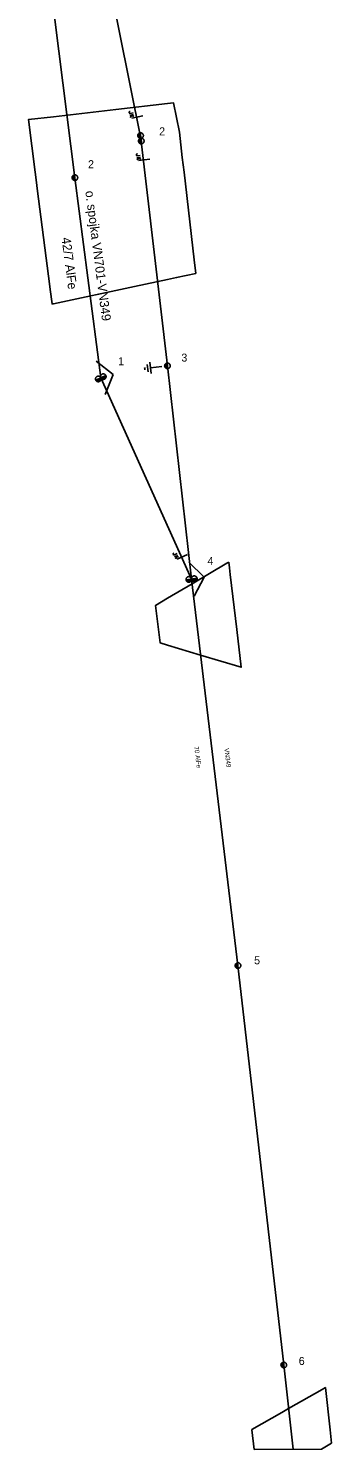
# Model space of a CAD drawing. Extents: x -536397 to -535454, y -1201642 to -1200953.
# Drawn here: x -536243 to -536176.6, y -1201641.8 to -1201331.1 of the extents above; entities that cross this region are included whole.
import ezdxf

# ---------------------------------------------------------------- set-up
doc = ezdxf.new("R2010")
doc.units = 0
for name, color, linetype in [('Vrstva 1', 7, 'Continuous'), ('Vrstva 13', 7, 'Continuous'), ('Vrstva 14', 7, 'Continuous'), ('Vrstva 15', 7, 'Continuous'), ('Vrstva 18', 7, 'Continuous'), ('Vrstva 2', 7, 'Continuous'), ('Vrstva 3', 7, 'Continuous'), ('Vrstva 35', 7, 'Continuous'), ('Vrstva 52', 7, 'Continuous'), ('Vrstva 53', 7, 'Continuous'), ('Vrstva 54', 7, 'Continuous')]:
    doc.layers.add(name, color=color, linetype=linetype)

# ---------------------------------------------------------------- blocks, each defined once
blk = doc.blocks.new('VN840')
at = {"layer": 'Vrstva 15'}
for points in [[(-0.01, 1.41), (-0.01, -1.09)], [(-1.51, -1.24), (-1.51, -1.15)], [(-1.48, -1.35), (-1.51, -1.24)], [(-1.33, -1.42), (-1.48, -1.35)], [(-1.27, -1.42), (-1.33, -1.42)], [(-1.13, -1.35), (-1.27, -1.42)], [(-1.09, -1.24), (-1.13, -1.35)], [(-1.09, -0.59), (-1.09, -1.24)], [(-0.68, -0.59), (-0.68, -1.42)], [(-0.68, -1.11), (-0.27, -0.59)], [(-0.54, -0.94), (-0.2, -1.42)]]:
    blk.add_lwpolyline(points, dxfattribs=at)
blk = doc.blocks.new('VN860')
at = {"layer": 'Vrstva 15'}
for points in [[(-3.74, 0), (0.01, 2.82)], [(0.01, 2.82), (3.76, 0)]]:
    blk.add_lwpolyline(points, dxfattribs=at)
blk = doc.blocks.new('VN440')
at = {"layer": 'Vrstva 2'}
for points in [[(1.22, 0), (1.21, 0.13), (1.19, 0.25), (1.16, 0.38), (1.11, 0.5), (1.05, 0.61), (0.98, 0.72), (0.9, 0.82), (0.81, 0.91), (0.71, 0.99), (0.6, 1.06), (0.49, 1.12), (0.37, 1.16), (0.25, 1.2), (0.12, 1.22), (-0.01, 1.22), (-0.14, 1.22), (-0.26, 1.2), (-0.39, 1.16), (-0.51, 1.12), (-0.62, 1.06), (-0.73, 0.99), (-0.83, 0.91), (-0.92, 0.82), (-1, 0.72), (-1.07, 0.61), (-1.13, 0.5), (-1.18, 0.38), (-1.21, 0.25), (-1.23, 0.13), (-1.24, 0), (-1.23, -0.13), (-1.21, -0.26), (-1.18, -0.38), (-1.13, -0.5), (-1.07, -0.62), (-1, -0.73), (-0.92, -0.83), (-0.83, -0.92), (-0.73, -1), (-0.62, -1.07), (-0.51, -1.13), (-0.39, -1.17), (-0.26, -1.2), (-0.14, -1.23), (-0.01, -1.23), (0.12, -1.23), (0.25, -1.2), (0.37, -1.17), (0.49, -1.13), (0.6, -1.07), (0.71, -1), (0.81, -0.92), (0.9, -0.83), (0.98, -0.73), (1.05, -0.62), (1.11, -0.5), (1.16, -0.38), (1.19, -0.26), (1.21, -0.13), (1.22, 0)], [(-1.24, 0), (1.22, 0)], [(-1.18, -0.34), (1.1, -0.34)], [(-1.01, -0.63), (0.97, -0.63)], [(-0.74, -0.92), (0.68, -0.92)]]:
    blk.add_lwpolyline(points, dxfattribs=at)
blk = doc.blocks.new('VN810')
at = {"layer": 'Vrstva 14'}
for points in [[(0, -1.25), (0, -3.75)], [(1.25, -3.75), (-1.25, -3.75)], [(0.77, -4.37), (-0.8, -4.37)], [(0, -5), (-0.25, -5)], [(0.27, -5), (0, -5)]]:
    blk.add_lwpolyline(points, dxfattribs=at)
blk = doc.blocks.new('VN450')
at = {"layer": 'Vrstva 2'}
for points in [[(0, 0), (-0.01, 0.13), (-0.03, 0.25), (-0.06, 0.38), (-0.11, 0.5), (-0.16, 0.61), (-0.23, 0.72), (-0.31, 0.82), (-0.4, 0.91), (-0.5, 0.99), (-0.61, 1.06), (-0.72, 1.11), (-0.84, 1.16), (-0.97, 1.19), (-1.09, 1.21), (-1.22, 1.22), (-1.35, 1.21), (-1.47, 1.19), (-1.59, 1.16), (-1.71, 1.11), (-1.83, 1.06), (-1.93, 0.99), (-2.03, 0.91), (-2.12, 0.82), (-2.2, 0.72), (-2.27, 0.61), (-2.33, 0.5), (-2.38, 0.38), (-2.41, 0.25), (-2.43, 0.13), (-2.44, 0), (-2.43, -0.13), (-2.41, -0.25), (-2.38, -0.38), (-2.33, -0.5), (-2.27, -0.61), (-2.2, -0.72), (-2.12, -0.82), (-2.03, -0.91), (-1.93, -0.99), (-1.83, -1.06), (-1.71, -1.11), (-1.59, -1.16), (-1.47, -1.19), (-1.35, -1.21), (-1.22, -1.22), (-1.09, -1.21), (-0.97, -1.19), (-0.84, -1.16), (-0.72, -1.11), (-0.61, -1.06), (-0.5, -0.99), (-0.4, -0.91), (-0.31, -0.82), (-0.23, -0.72), (-0.16, -0.61), (-0.11, -0.5), (-0.06, -0.38), (-0.03, -0.25), (-0.01, -0.13), (0, 0)], [(-2.44, 0), (2.44, 0)], [(2.44, 0), (2.43, 0.13), (2.41, 0.25), (2.38, 0.38), (2.33, 0.5), (2.27, 0.61), (2.2, 0.72), (2.12, 0.82), (2.03, 0.91), (1.94, 0.99), (1.83, 1.06), (1.71, 1.11), (1.6, 1.16), (1.47, 1.19), (1.35, 1.21), (1.22, 1.22), (1.09, 1.21), (0.97, 1.19), (0.84, 1.16), (0.72, 1.11), (0.61, 1.06), (0.5, 0.99), (0.4, 0.91), (0.31, 0.82), (0.23, 0.72), (0.16, 0.61), (0.11, 0.5), (0.06, 0.38), (0.03, 0.25), (0.01, 0.13), (0, 0), (0.01, -0.13), (0.03, -0.25), (0.06, -0.38), (0.11, -0.5), (0.16, -0.61), (0.23, -0.72), (0.31, -0.82), (0.4, -0.91), (0.5, -0.99), (0.61, -1.06), (0.72, -1.11), (0.84, -1.16), (0.97, -1.19), (1.09, -1.21), (1.22, -1.22), (1.35, -1.21), (1.47, -1.19), (1.6, -1.16), (1.71, -1.11), (1.83, -1.06), (1.94, -0.99), (2.03, -0.91), (2.12, -0.82), (2.2, -0.72), (2.27, -0.61), (2.33, -0.5), (2.38, -0.38), (2.41, -0.25), (2.43, -0.13), (2.44, 0)], [(-2.4, -0.31), (-0.04, -0.31)], [(-2.26, -0.61), (-0.17, -0.61)], [(-2.01, -0.92), (-0.42, -0.92)], [(0.04, -0.31), (2.4, -0.31)], [(0.17, -0.61), (2.27, -0.61)], [(0.42, -0.92), (2.02, -0.92)]]:
    blk.add_lwpolyline(points, dxfattribs=at)

msp = doc.modelspace()

# ---------------------------------------------------------------- linework, layer by layer
at = {"layer": 'Vrstva 1'}
for points in [[(-536230.2, -1201296.37), (-536218.34, -1201355.12), (-536212.54, -1201404.88), (-536207.27, -1201451.49)], [(-536207.27, -1201451.49), (-536197.12, -1201536.02), (-536187.09, -1201623.35), (-536185.03, -1201641.79)]]:
    msp.add_lwpolyline(points, dxfattribs=at)
at = {"layer": 'Vrstva 35'}
for points in [[(-536223.8, -1201348.8), (-536212.5, -1201347.49), (-536211.24, -1201347.33), (-536209.94, -1201353.78), (-536209.3, -1201359.3), (-536208.92, -1201362.5), (-536206.69, -1201381.69), (-536206.34, -1201384.65), (-536210.55, -1201385.55), (-536212.5, -1201385.96), (-536219.72, -1201387.5), (-536237.5, -1201391.29), (-536237.79, -1201391.34), (-536238.2, -1201388.2), (-536238.29, -1201387.5), (-536241.06, -1201366.06), (-536241.22, -1201364.8), (-536241.51, -1201362.5), (-536242.96, -1201351.03), (-536237.5, -1201350.39)], [(-536199.14, -1201447.78), (-536199, -1201449), (-536198.83, -1201450.48), (-536198.83, -1201450.51), (-536198.82, -1201450.53), (-536197.38, -1201462.5), (-536196.39, -1201470.78), (-536205.28, -1201468.1), (-536212.5, -1201465.93), (-536214.16, -1201465.43), (-536214.3, -1201464.3), (-536214.51, -1201462.5), (-536215.14, -1201457.24), (-536212.5, -1201455.68), (-536207.15, -1201452.51), (-536199.52, -1201448.01)], [(-536193.58, -1201641.85), (-536194.07, -1201637.5), (-536194.07, -1201637.47), (-536187.5, -1201633.73), (-536186.03, -1201632.89), (-536178.71, -1201628.71), (-536177.98, -1201628.3), (-536176.96, -1201637.5), (-536176.63, -1201640.42), (-536178.82, -1201641.75)]]:
    msp.add_lwpolyline(points, close=True, dxfattribs=at)
at = {"layer": 'Vrstva 52'}
msp.add_lwpolyline([(-536238.92, -1201315.23), (-536232.79, -1201363.72), (-536227.13, -1201407.48), (-536207.27, -1201451.49)], dxfattribs=at)

# ---------------------------------------------------------------- block references
at = {"layer": 'Vrstva 13'}
for name, p, xscale, yscale, rotation in [('VN450', (-536218.34, -1201355.12), 0.49999999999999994, 0.5000000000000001, -82.37695835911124), ('VN440', (-536232.79, -1201363.72), 0.5000000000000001, 0.5, -82.79528052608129), ('VN450', (-536227.13, -1201407.48), 0.5, 0.5, 24.700652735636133), ('VN440', (-536212.54, -1201404.88), 0.5, 0.5000000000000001, -83.35179166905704), ('VN450', (-536207.27, -1201451.49), 0.5, 0.5, 7.6230417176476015), ('VN440', (-536197.12, -1201536.02), 0.5000000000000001, 0.5, -83.15304168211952), ('VN440', (-536187.09, -1201623.35), 0.5, 0.5, -83.44827777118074)]:
    msp.add_blockref(name, p, dxfattribs=dict(at, xscale=xscale, yscale=yscale, rotation=rotation))
at = {"layer": 'Vrstva 15', "rotation": -83.35240554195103}
msp.add_blockref('VN810', (-536212.54, -1201404.88), dxfattribs=at)
at = {"layer": 'Vrstva 18'}
for name, p, rotation in [('VN840', (-536219.28, -1201350.48), -78.58695282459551), ('VN840', (-536217.78, -1201359.88), -83.35163336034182), ('VN860', (-536227.13, -1201407.48), -74.68854724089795), ('VN840', (-536209.44, -1201446.68), -65.71219719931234), ('VN860', (-536207.27, -1201451.49), -81.0083778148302)]:
    msp.add_blockref(name, p, dxfattribs=dict(at, rotation=rotation))

# ---------------------------------------------------------------- texts
at = {"layer": 'Vrstva 14'}
for s, p in [('2', (-536214.36, -1201354.47)), ('2', (-536229.92, -1201361.65)), ('1', (-536223.33, -1201404.74)), ('3', (-536209.5, -1201403.94)), ('4', (-536203.79, -1201448.39)), ('5', (-536193.58, -1201535.73)), ('6', (-536183.82, -1201623.34))]:
    msp.add_text(s, height=1.75, dxfattribs=at).set_placement(p)
at = {"layer": 'Vrstva 2'}
msp.add_text('70 AlFe', height=1, rotation=276.847, dxfattribs=at).set_placement((-536206.69, -1201488.14))
at = {"layer": 'Vrstva 3'}
msp.add_text('VN349', height=1, rotation=276.847, dxfattribs=at).set_placement((-536200.1, -1201488.54))
at = {"layer": 'Vrstva 53'}
msp.add_text('42/7 AlFe', height=2, rotation=277.37, dxfattribs=at).set_placement((-536235.72, -1201376.89))
at = {"layer": 'Vrstva 54'}
msp.add_text('o. spojka VN701-VN349', height=2, rotation=277.37, dxfattribs=at).set_placement((-536230.52, -1201366.7))

doc.saveas('drawing.dxf')
